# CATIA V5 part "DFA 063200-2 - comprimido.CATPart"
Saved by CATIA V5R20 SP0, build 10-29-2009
Part number: DFA 063200-2 - comprimido
Revision: ANY
Definition: UNKNOWN
Nomenclature: DFA 063200-2 - comprimido
Source: Unknown
Bounding box of the stored display mesh (mm): x -1.95 to 1.95, y 0 to 5.85, z -1.95 to 1.95
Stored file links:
  C:\Users\Utente\Desktop\IO LAVORO\3D X SITO CF\CUMSA\3D files FA\FA 063205-21\DFA 063200-2 - comprimido.CATPart

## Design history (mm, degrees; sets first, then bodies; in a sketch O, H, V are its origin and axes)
Body1 "Cortar-Extruir1" (main body)
  Solid1: solid without history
